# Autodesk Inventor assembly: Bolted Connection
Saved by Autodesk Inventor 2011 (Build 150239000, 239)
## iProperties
Created: 2020-12
Part Number: Bolted Connection
Document SubType Name: Assembly
Designer: PC
ClientObjectVersion: 1
Author: PC
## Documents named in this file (3)
- C:\Users\PC\Documents\Inventor\workshop-crane-powered-by-drill\estructura-principal\Design Accelerator\Bolted Connection3.iam
- C:\Users\PC\Documents\Inventor\Content Center Files\R2011\en-US\DIN 931-1\DIN 931-1 - M14 x 90.ipt
- C:\Users\PC\Documents\Inventor\Content Center Files\R2011\en-US\DIN 555\DIN 555-5 - M14.ipt
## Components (2 placed, 2 different names)
1. DIN 931-1 - replaced by DIN EN 24014 M14 x 90:1
2. DIN 555 - replaced by DIN EN 24034 M14:1
